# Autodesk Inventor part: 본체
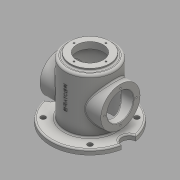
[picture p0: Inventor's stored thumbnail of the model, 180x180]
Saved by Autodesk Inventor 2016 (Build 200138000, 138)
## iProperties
Created: 2018-04
Part Number: 본체
Material: 일반
Document SubType Name: Modeling
Designer: 605-15
Density: 1 g/cm^3
Appearance: 기본값
Author: 605-15
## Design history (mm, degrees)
sketch "스케치1"
  geometry: C1 r 50 at (0, 0); 1 further point
  constraints: 1 centre point, 1 coincident
  dimensions: "d0" = 100 diameter of C1
extrude "돌출1" new body sketch "스케치1" distance "d1" = 8; taper "d2" = 0 deg
sketch "스케치2"
  geometry: C1 r 80 at (0, 0); 1 further point
  constraints: 1 centre point, 1 coincident
  dimensions: "d3" = 160 diameter of C1
extrude "돌출2" join sketch "스케치2" distance "d4" = 10; taper "d5" = 0 deg
sketch "스케치3"
  geometry: C1 r 50 at (0, 0); 1 further point
  constraints: 1 centre point, 1 coincident
  dimensions: "d6" = 100 diameter of C1
extrude "돌출3" join sketch "스케치3" distance "d7" = 110; taper "d8" = 0 deg
sketch "스케치4"
  geometry: C1 r 40 at (0, 0); 1 further point
  constraints: 1 centre point, 1 coincident
  dimensions: "d9" = 80 diameter of C1
extrude "돌출4" join sketch "스케치4" distance "d10" = 5; taper "d11" = 0 deg
sketch "스케치7"
  geometry: L1 (-80, 8)-(80, 8) reference; L2 (50, 8)-(-50, 8) reference; L3 (0, 8)-(0, 68); C1 r 40 at (0, 68); 1 further point
  constraints: 2 end point, 1 centre point, 1 coincident, 1 midpoint, 1 vertical
  dimensions: "d18" = 60 distance of L3.start L3.end; "d19" = 80 diameter of C1
extrude "돌출7" join sketch "스케치7" stored distance "d20" = 124; taper "d21" = 0 deg
sketch "스케치8"
  geometry: C1 r 27 at (0, 0); 1 further point
  constraints: 1 centre point
  dimensions: "d22" = 54 diameter of C1
extrude "돌출8" cut sketch "스케치8" stored distance "d23" = 124; taper "d24" = 0 deg
sketch "스케치9"
  geometry: C1 r 45 at (0, 0); 1 further point
  constraints: 1 centre point, 1 coincident
  dimensions: "d25" = 90 diameter of C1
extrude "돌출9" cut sketch "스케치9" distance "d26" = 120; taper "d27" = 0 deg
sketch "스케치10"
  geometry: C1 r 27 at (0, 0); 1 further point
  constraints: 1 centre point, 1 coincident
  dimensions: "d28" = 54 diameter of C1
extrude "돌출10" cut sketch "스케치10" distance "d29" = 13; taper "d30" = 0 deg
sketch "스케치11"
  geometry: A1 r 32.5 centre (0, 0) between (0, 32.5) and (32.5, 0); 3 further points
  constraints: 4 point on circle, 1 centre point, 1 coincident
  dimensions: "d31" = 65 diameter of A1
hole "구멍1" sketch "스케치11" at (0, 32.5), (32.5, 0), (0, -32.5), (-32.5, 0) diameter "d32" = 3.242; stored, may be unused: countersink angle "d36" = 90 deg, drill point angle "d38" = 118 deg; dims "d33" = 8, "d34" = 4, "d35" = 2, "d37" = 10
sketch "스케치12"
  geometry: A1 r 32.5 centre (0, 0) between (32.5, 0) and (0, -32.5); 3 further points
  constraints: 4 point on circle, 1 centre point
  dimensions: "d39" = 65 diameter of A1
hole "구멍2" sketch "스케치12" at (32.5, 0), (0, -32.5), (-32.5, 0), (0, 32.5) diameter "d40" = 3.242; stored, may be unused: countersink angle "d44" = 90 deg, drill point angle "d46" = 118 deg; dims "d41" = 8, "d42" = 4, "d43" = 2, "d45" = 10
sketch "스케치13"
  geometry: C1 r 15 at (-80, 0); C2 r 15 at (80, 0); A1 r 80 centre (0, 0) between (-80, 0) and (80, 0) reference; 1 further point
  constraints: 2 centre point, 2 point on circle
  dimensions: "d49" = 30 diameter of C1; "d50" = 30 diameter of C2
extrude "돌출11" cut sketch "스케치13" stored distance "d51" = 13; taper "d52" = 0 deg
sketch "스케치14"
  geometry: L1 (0, 0)-(0, 80); L2 (0, 0)-(74.498, 74.498); L3 (0, 0)-(0, -80); L4 (0, 0)-(98.351, -98.351); C1 r 5 at (47.73, 47.73); C2 r 5 at (47.73, -47.73); A1 r 80 centre (0, 0) between (78.594, 14.934) and (-78.594, 14.934) reference; A2 r 67.5 centre (0, 0) between (47.73, 47.73) and (47.73, -47.73)
  constraints: 8 end point, 3 centre point, 3 point on circle, 2 point on line, 2 vertical, 1 coincident
  dimensions: "d53" = 45 deg angle of L1 L2; "d54" = 45 deg angle of L4 L3; "d55" = 135 diameter of A2; "d56" = 10 diameter of C1; "d57" = 10 diameter of C2
extrude "돌출12" cut sketch "스케치14" stored distance "d58" = 13; taper "d59" = 0 deg
node "작업 평면1"
node "작업 평면2"
sketch "스케치15"
  geometry: L1 (-6.424, 52.038)-(-6.424, 103.962); L2 (-6.424, 103.962)-(6.424, 103.962); L3 (6.424, 103.962)-(6.424, 52.038); L4 (6.424, 52.038)-(-6.424, 52.038); L5 (0, 103.962)-(0, 52.038); L6 (6.424, 78)-(-6.424, 78); L7 (50, 8)-(-50, 8) reference; L8 (0, 8)-(0, 78); 2 further points
  constraints: 6 end point, 6 midpoint, 1 vertical, 2 other
  dimensions: "d74" = 70 distance of L8.start L8.end
feature "엠보싱1" sketch "스케치15" dims "d62" = 0.5, "d63" = 0
fillet "모깎기1" dims "d64" = 3
fillet "모깎기3" dims "d66" = 3
chamfer "모따기1" distance "d67" = 1; stored, may be unused: second distance "d68" = 2, angle "d69" = 45 deg
fillet "모깎기4" dims "d70" = 3
fillet "모깎기5" dims "d71" = 3, "d72" = 5
node "솔리드1"
mirror "대칭1"
mirror "대칭2"
other parameters: "d60" = -147.25
